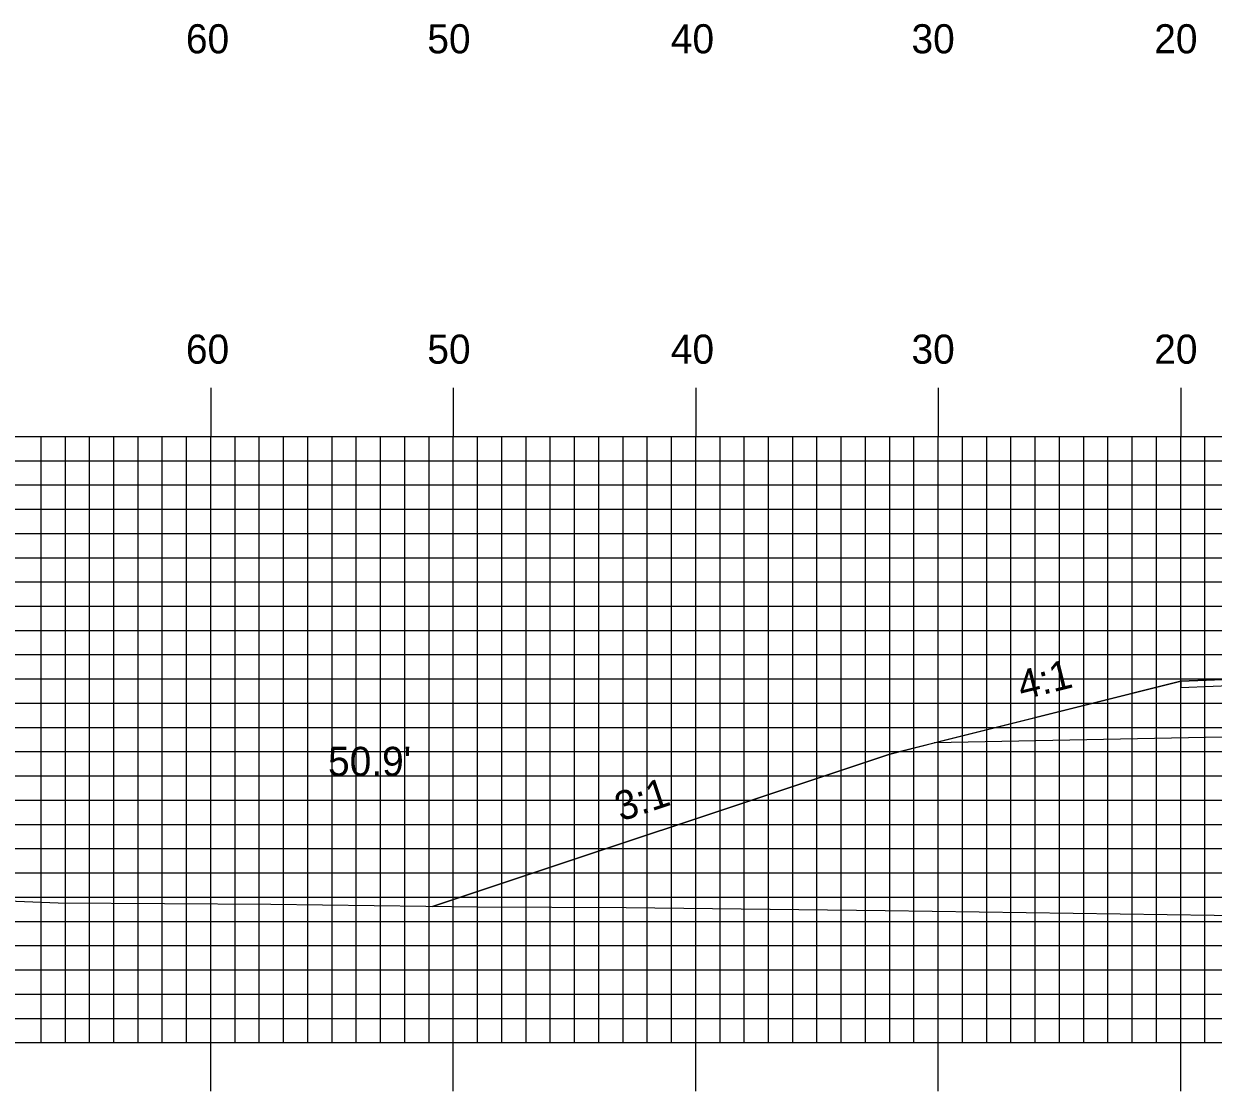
# Model space of a CAD drawing. Extents: x 1819244 to 1819587, y 442591 to 442811.
# Drawn here: x 1819341.95 to 1819391.01, y 442696.66 to 442740.68 of the extents above; entities that cross this region are included whole.
import ezdxf

# ---------------------------------------------------------------- set-up
doc = ezdxf.new("R2010")
doc.units = 0
for name, color, linetype in [('ANNOTATION', 7, 'Continuous'), ('D_Roadway_Centerline', 7, 'Continuous'), ('D_Roadway_Edge_Shoulder', 7, 'Continuous'), ('D_Roadway_SlopeLines', 7, 'Continuous'), ('D_Roadway_SubGrade', 7, 'Continuous'), ('D_Text_Standard', 7, 'Continuous'), ('H_V ANNOTATION', 7, 'Continuous'), ('MAJOR', 7, 'Continuous'), ('MINOR', 7, 'Continuous'), ('S_Roadway_Centerline', 7, 'Continuous')]:
    doc.layers.add(name, color=color, linetype=linetype)

msp = doc.modelspace()

# ---------------------------------------------------------------- linework, layer by layer
at = {"layer": 'D_Roadway_Centerline'}
msp.add_lwpolyline([(1819358.814, 442704.283), (1819377.665, 442710.567), (1819379.491, 442711.023), (1819389.665, 442713.567), (1819397.665, 442713.887), (1819409.665, 442714.127), (1819421.665, 442713.887), (1819429.665, 442713.567), (1819439.839, 442711.023), (1819441.665, 442710.567), (1819459.682, 442704.561)], dxfattribs=at)
at = {"layer": 'D_Roadway_Edge_Shoulder'}
msp.add_lwpolyline([(1819397.665, 442713.887), (1819389.665, 442713.567), (1819389.665, 442713.317), (1819397.665, 442713.637)], close=True, dxfattribs=at)
at = {"layer": 'D_Roadway_SlopeLines'}
msp.add_lwpolyline([(1819389.665, 442713.567), (1819377.665, 442710.567), (1819358.814, 442704.283)], dxfattribs=at)
at = {"layer": 'D_Roadway_SubGrade'}
msp.add_lwpolyline([(1819397.665, 442711.387), (1819379.491, 442711.023), (1819389.665, 442713.567), (1819389.665, 442713.317), (1819397.665, 442713.637), (1819409.665, 442713.877), (1819421.665, 442713.637), (1819429.665, 442713.317), (1819429.665, 442713.567), (1819439.839, 442711.023), (1819421.665, 442711.387), (1819409.665, 442711.627)], close=True, dxfattribs=at)
at = {"layer": 'MAJOR'}
for p, q in [((1819349.665, 442725.669), (1819349.665, 442723.665)), ((1819359.665, 442725.669), (1819359.665, 442723.665)), ((1819369.665, 442725.669), (1819369.665, 442723.665)), ((1819379.665, 442725.669), (1819379.665, 442723.665)), ((1819389.665, 442725.669), (1819389.665, 442723.665)), ((1819269.665, 442723.665), (1819549.665, 442723.665)), ((1819269.665, 442723.665), (1819549.665, 442723.665)), ((1819349.665, 442698.665), (1819349.665, 442723.665)), ((1819359.665, 442698.665), (1819359.665, 442723.665)), ((1819369.665, 442698.665), (1819369.665, 442723.665)), ((1819379.665, 442698.665), (1819379.665, 442723.665)), ((1819389.665, 442698.665), (1819389.665, 442723.665)), ((1819269.665, 442718.665), (1819549.665, 442718.665)), ((1819269.665, 442713.665), (1819549.665, 442713.665)), ((1819269.665, 442708.665), (1819549.665, 442708.665)), ((1819269.665, 442703.665), (1819549.665, 442703.665)), ((1819269.665, 442698.665), (1819549.665, 442698.665)), ((1819269.665, 442698.665), (1819549.665, 442698.665)), ((1819349.665, 442696.661), (1819349.665, 442698.665)), ((1819359.665, 442696.661), (1819359.665, 442698.665)), ((1819369.665, 442696.661), (1819369.665, 442698.665)), ((1819379.665, 442696.661), (1819379.665, 442698.665)), ((1819389.665, 442696.661), (1819389.665, 442698.665))]:
    msp.add_line(p, q, dxfattribs=at)
at = {"layer": 'MINOR'}
for p, q in [((1819342.665, 442698.665), (1819342.665, 442723.665)), ((1819343.665, 442698.665), (1819343.665, 442723.665)), ((1819344.665, 442698.665), (1819344.665, 442723.665)), ((1819345.665, 442698.665), (1819345.665, 442723.665)), ((1819346.665, 442698.665), (1819346.665, 442723.665)), ((1819347.665, 442698.665), (1819347.665, 442723.665)), ((1819348.665, 442698.665), (1819348.665, 442723.665)), ((1819350.665, 442698.665), (1819350.665, 442723.665)), ((1819351.665, 442698.665), (1819351.665, 442723.665)), ((1819352.665, 442698.665), (1819352.665, 442723.665)), ((1819353.665, 442698.665), (1819353.665, 442723.665)), ((1819354.665, 442698.665), (1819354.665, 442723.665)), ((1819355.665, 442698.665), (1819355.665, 442723.665)), ((1819356.665, 442698.665), (1819356.665, 442723.665)), ((1819357.665, 442698.665), (1819357.665, 442723.665)), ((1819358.665, 442698.665), (1819358.665, 442723.665)), ((1819360.665, 442698.665), (1819360.665, 442723.665)), ((1819361.665, 442698.665), (1819361.665, 442723.665)), ((1819362.665, 442698.665), (1819362.665, 442723.665)), ((1819363.665, 442698.665), (1819363.665, 442723.665)), ((1819364.665, 442698.665), (1819364.665, 442723.665)), ((1819365.665, 442698.665), (1819365.665, 442723.665)), ((1819366.665, 442698.665), (1819366.665, 442723.665)), ((1819367.665, 442698.665), (1819367.665, 442723.665)), ((1819368.665, 442698.665), (1819368.665, 442723.665)), ((1819370.665, 442698.665), (1819370.665, 442723.665)), ((1819371.665, 442698.665), (1819371.665, 442723.665)), ((1819372.665, 442698.665), (1819372.665, 442723.665)), ((1819373.665, 442698.665), (1819373.665, 442723.665)), ((1819374.665, 442698.665), (1819374.665, 442723.665)), ((1819375.665, 442698.665), (1819375.665, 442723.665)), ((1819376.665, 442698.665), (1819376.665, 442723.665)), ((1819377.665, 442698.665), (1819377.665, 442723.665)), ((1819378.665, 442698.665), (1819378.665, 442723.665)), ((1819380.665, 442698.665), (1819380.665, 442723.665)), ((1819381.665, 442698.665), (1819381.665, 442723.665)), ((1819382.665, 442698.665), (1819382.665, 442723.665)), ((1819383.665, 442698.665), (1819383.665, 442723.665)), ((1819384.665, 442698.665), (1819384.665, 442723.665)), ((1819385.665, 442698.665), (1819385.665, 442723.665)), ((1819386.665, 442698.665), (1819386.665, 442723.665)), ((1819387.665, 442698.665), (1819387.665, 442723.665)), ((1819388.665, 442698.665), (1819388.665, 442723.665)), ((1819390.665, 442698.665), (1819390.665, 442723.665)), ((1819269.665, 442722.665), (1819549.665, 442722.665)), ((1819269.665, 442721.665), (1819549.665, 442721.665)), ((1819269.665, 442720.665), (1819549.665, 442720.665)), ((1819269.665, 442719.665), (1819549.665, 442719.665)), ((1819269.665, 442717.665), (1819549.665, 442717.665)), ((1819269.665, 442716.665), (1819549.665, 442716.665)), ((1819269.665, 442715.665), (1819549.665, 442715.665)), ((1819269.665, 442714.665), (1819549.665, 442714.665)), ((1819269.665, 442712.665), (1819549.665, 442712.665)), ((1819269.665, 442711.665), (1819549.665, 442711.665)), ((1819269.665, 442710.665), (1819549.665, 442710.665)), ((1819269.665, 442709.665), (1819549.665, 442709.665)), ((1819269.665, 442707.665), (1819549.665, 442707.665)), ((1819269.665, 442706.665), (1819549.665, 442706.665)), ((1819269.665, 442705.665), (1819549.665, 442705.665)), ((1819269.665, 442704.665), (1819549.665, 442704.665)), ((1819269.665, 442702.665), (1819549.665, 442702.665)), ((1819269.665, 442701.665), (1819549.665, 442701.665)), ((1819269.665, 442700.665), (1819549.665, 442700.665)), ((1819269.665, 442699.665), (1819549.665, 442699.665))]:
    msp.add_line(p, q, dxfattribs=at)
at = {"layer": 'S_Roadway_Centerline'}
msp.add_lwpolyline([(1819269.665, 442707.687), (1819275.474, 442707.504), (1819284.498, 442706.654), (1819292.722, 442706.103), (1819298.733, 442705.742), (1819320.061, 442705.217), (1819325.548, 442705.085), (1819329.093, 442704.993), (1819343.369, 442704.432), (1819352.14, 442704.37), (1819360.662, 442704.259), (1819366.793, 442704.236), (1819377.474, 442704.109), (1819392.989, 442703.895), (1819394.88, 442703.882), (1819406.852, 442704.112), (1819411.995, 442704.538), (1819419.819, 442704.684), (1819427.778, 442704.423), (1819453.028, 442704.68), (1819462.649, 442704.508), (1819470.362, 442704.387), (1819486.238, 442704.118)], dxfattribs=at)

# ---------------------------------------------------------------- texts
at = {"layer": 'ANNOTATION'}
for s, rotation, p in [('4:1', 14.0362, (1819383.113, 442712.79)), ('3:1', 18.4348, (1819366.578, 442707.779))]:
    msp.add_text(s, height=1.2, rotation=rotation, dxfattribs=at).set_placement(p)
at = {"layer": 'D_Text_Standard'}
msp.add_text("50.9'", height=1.2, dxfattribs=at).set_placement((1819354.499, 442709.665))
at = {"layer": 'H_V ANNOTATION'}
for s, p in [('60', (1819348.637, 442739.465)), ('50', (1819358.594, 442739.465)), ('40', (1819368.637, 442739.465)), ('30', (1819378.562, 442739.465)), ('20', (1819388.573, 442739.465)), ('60', (1819348.637, 442726.665)), ('50', (1819358.594, 442726.665)), ('40', (1819368.637, 442726.665)), ('30', (1819378.562, 442726.665)), ('20', (1819388.573, 442726.665))]:
    msp.add_text(s, height=1.2, dxfattribs=at).set_placement(p)

doc.saveas('drawing.dxf')
